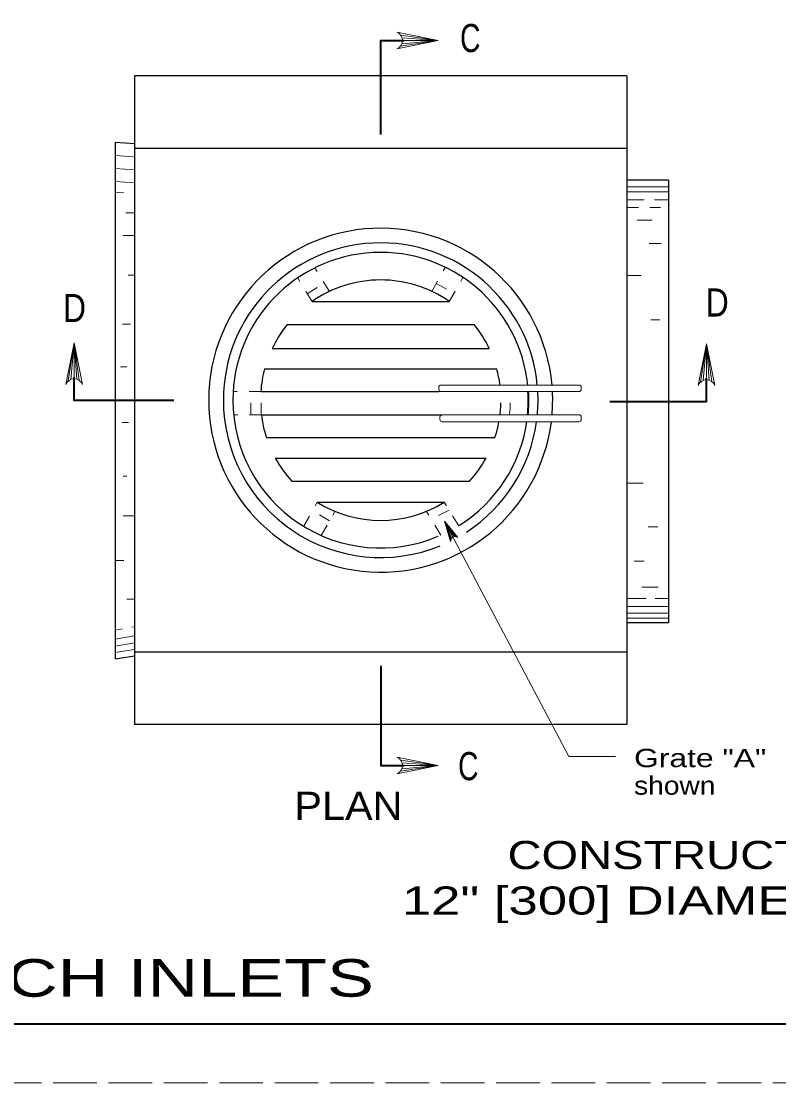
# Model space of a CAD drawing. Extents: x 1036.7 to 1070.7, y 883.9 to 905.9.
# Drawn here: x 1051.03 to 1057.49, y 883.91 to 892.96 of the extents above; entities that cross this region are included whole.
import ezdxf
from ezdxf.enums import TextEntityAlignment as Align

# ---------------------------------------------------------------- set-up
doc = ezdxf.new("R2010")
doc.units = 0
doc.header["$LTSCALE"] = 0.062
doc.linetypes.add('LONG_DASHED', pattern=[7.5, 6, -1.5])
doc.linetypes.add('SHORT_DASHED', pattern=[2.7, 1.5, -1.2])
doc.layers.add('1', color=7, linetype='Continuous', lineweight=13)

msp = doc.modelspace()

# ---------------------------------------------------------------- linework, layer by layer
at = {"layer": '1'}
for p, q in [((1054.26425, 892.74675), (1054.5885, 892.79633)), ((1054.268, 892.84117), (1054.5885, 892.79633)), ((1054.2765, 892.7675), (1054.5885, 892.79633)), ((1054.27892, 892.81892), (1054.5885, 892.79633)), ((1054.28217, 892.79633), (1054.5885, 892.79633)), ((1051.83217, 891.81367), (1051.99033, 891.80275)), ((1051.83217, 891.70508), (1051.99825, 891.69367)), ((1051.83217, 891.59333), (1051.99825, 891.58183)), ((1051.83217, 891.502), (1051.90658, 891.49683)), ((1056.19583, 891.54758), (1056.55183, 891.54758)), ((1056.19583, 891.50567), (1056.55183, 891.50567)), ((1056.19583, 891.4365), (1056.34217, 891.4365)), ((1056.43225, 891.4365), (1056.55183, 891.4365)), ((1051.92533, 891.32533), (1051.99825, 891.32533)), ((1056.19583, 891.3725), (1056.29525, 891.3725)), ((1056.39158, 891.3725), (1056.48383, 891.3725)), ((1056.2835, 891.26333), (1056.41108, 891.26333)), ((1051.90225, 891.13333), (1051.99825, 891.13333)), ((1056.38533, 891.06517), (1056.48858, 891.06517)), ((1051.9445, 890.7955), (1051.99825, 890.7955)), ((1056.19583, 890.791), (1056.31667, 890.791)), ((1056.40142, 890.41283), (1056.4775, 890.41283)), ((1051.89458, 890.37692), (1051.96367, 890.37692)), ((1051.433, 889.89275), (1051.48258, 890.217)), ((1051.45375, 889.905), (1051.48258, 890.217)), ((1051.48258, 889.91067), (1051.48258, 890.217)), ((1051.50525, 889.90733), (1051.48258, 890.217)), ((1051.52742, 889.8965), (1051.48258, 890.217)), ((1056.82508, 889.88358), (1056.87458, 890.20783)), ((1056.84583, 889.89583), (1056.87458, 890.20783)), ((1056.87458, 889.9015), (1056.87458, 890.20783)), ((1056.89725, 889.89817), (1056.87458, 890.20783)), ((1056.91942, 889.88733), (1056.87458, 890.20783)), ((1051.87933, 890.01208), (1051.933, 890.01208)), ((1054.59267, 889.83683), (1054.59267, 889.82117)), ((1054.59267, 889.80125), (1055.78667, 889.80125)), ((1054.61267, 889.85683), (1055.78667, 889.85683)), ((1055.80667, 889.83683), (1055.80667, 889.82117)), ((1054.6225, 889.60492), (1055.78667, 889.60492)), ((1051.89358, 889.53692), (1051.94733, 889.53692)), ((1054.6025, 889.58492), (1054.6025, 889.56492)), ((1054.6225, 889.54492), (1055.78667, 889.54492)), ((1055.80667, 889.58492), (1055.80667, 889.56492)), ((1051.90183, 889.08083), (1051.93117, 889.08083)), ((1056.19583, 889.0215), (1056.33592, 889.0215)), ((1051.90167, 888.74167), (1051.99825, 888.74167)), ((1054.71342, 888.56108), (1054.64175, 888.69642)), ((1054.70208, 888.55183), (1054.64175, 888.69642)), ((1054.69575, 888.54158), (1054.64175, 888.69642)), ((1054.72425, 888.56492), (1054.64175, 888.69642)), ((1054.73658, 888.56533), (1054.64175, 888.69642)), ((1056.37817, 888.6475), (1056.4605, 888.6475)), ((1051.83217, 888.36217), (1051.907, 888.36217)), ((1056.25892, 888.35708), (1056.34233, 888.35708)), ((1056.32342, 888.13442), (1056.46342, 888.13442)), ((1051.9315, 888.03108), (1051.99825, 888.03108)), ((1056.19583, 888.03842), (1056.36167, 888.03842)), ((1056.19583, 887.96958), (1056.55183, 887.96958)), ((1056.4365, 888.03842), (1056.55183, 888.03842)), ((1056.19583, 887.91333), (1056.55183, 887.91333)), ((1056.19583, 887.87025), (1056.55183, 887.87025)), ((1051.97592, 887.792), (1051.99825, 887.79558)), ((1051.83217, 887.76875), (1051.89608, 887.77908)), ((1051.83217, 887.69183), (1051.99825, 887.71875)), ((1051.83217, 887.63133), (1051.99825, 887.65817)), ((1051.83217, 887.57642), (1051.99825, 887.60333)), ((1054.26425, 886.564), (1054.5885, 886.61358)), ((1054.268, 886.65842), (1054.5885, 886.61358)), ((1054.2765, 886.58475), (1054.5885, 886.61358)), ((1054.27892, 886.63625), (1054.5885, 886.61358)), ((1054.28217, 886.61358), (1054.5885, 886.61358))]:
    msp.add_line(p, q, dxfattribs=at)
at = {"layer": '1', "lineweight": 25}
for p, q in [((1056.19583, 892.494), (1051.99825, 892.494)), ((1051.99825, 892.494), (1051.99825, 886.96275)), ((1056.19583, 892.494), (1056.19583, 886.96275)), ((1051.83217, 891.92808), (1051.83217, 887.52317)), ((1051.83217, 891.92808), (1051.99825, 891.91658)), ((1056.19583, 891.87417), (1051.99825, 891.87417)), ((1056.55183, 891.60392), (1056.19583, 891.60392)), ((1056.55183, 891.60392), (1056.55183, 887.829)), ((1053.51208, 890.57025), (1054.68208, 890.57025)), ((1053.30092, 890.37425), (1054.89333, 890.37425)), ((1053.17125, 890.16875), (1055.02292, 890.16875)), ((1053.10758, 889.99633), (1055.08658, 889.99633)), ((1053.0745, 889.80125), (1054.59267, 889.80125)), ((1053.07933, 889.60492), (1054.6225, 889.60492)), ((1053.12283, 889.40933), (1055.07142, 889.40933)), ((1053.1985, 889.23492), (1054.99567, 889.23492)), ((1053.33858, 889.03875), (1054.85558, 889.03875)), ((1053.55533, 888.85808), (1054.63875, 888.85808)), ((1056.55183, 887.829), (1056.19583, 887.829)), ((1051.83217, 887.52317), (1051.99825, 887.55008)), ((1056.19583, 887.57975), (1051.99825, 887.57975)), ((1056.19583, 886.96275), (1051.99825, 886.96275))]:
    msp.add_line(p, q, dxfattribs=at)
at = {"layer": '1', "linetype": 'SHORT_DASHED'}
for p, q in [((1054.53292, 890.65633), (1054.64858, 890.86175)), ((1053.51208, 890.57025), (1053.38917, 890.77125)), ((1053.65925, 890.65533), (1053.53583, 890.857)), ((1054.68208, 890.57025), (1054.79792, 890.77608)), ((1053.4715, 890.63658), (1053.61642, 890.72525)), ((1054.57108, 890.72417), (1054.72233, 890.64192)), ((1053.0745, 889.80125), (1052.83867, 889.80125)), ((1052.99092, 889.60492), (1052.99092, 889.80125)), ((1053.07933, 889.60492), (1053.0745, 889.80125)), ((1053.07933, 889.60492), (1052.84258, 889.60492)), ((1053.43967, 888.65267), (1053.55533, 888.85808)), ((1053.66175, 888.70092), (1053.51375, 888.78442)), ((1053.5905, 888.57433), (1053.70667, 888.78058)), ((1054.611, 888.57758), (1054.487, 888.78042)), ((1054.67958, 888.79142), (1054.52717, 888.71483)), ((1054.76208, 888.65642), (1054.63875, 888.85808))]:
    msp.add_line(p, q, dxfattribs=at)
at = {"layer": '1', "linetype": 'LONG_DASHED'}
msp.add_lwpolyline([(1036.67333, 883.90825), (1070.67333, 883.90825), (1070.67333, 905.90825), (1036.67333, 905.90825)], close=True, dxfattribs=at)
at = {"layer": '1', "lineweight": 25}
msp.add_lwpolyline([(1070.17333, 884.40825), (1038.67333, 884.40825), (1038.67333, 905.40825)], dxfattribs=at)
at = {"layer": '1', "lineweight": 40}
msp.add_lwpolyline([(1038.67333, 905.40825), (1070.17333, 905.40825), (1070.17333, 884.40825), (1038.67333, 884.40825)], close=True, dxfattribs=at)
msp.add_lwpolyline([(1038.67333, 905.40825), (1070.17333, 905.40825), (1070.17333, 884.40825), (1038.67333, 884.40825)], close=True, dxfattribs=at)
at = {"layer": '1'}
for points in [[(1054.2345, 892.7255), (1054.5885, 892.79633), (1054.2345, 892.86708)], [(1051.41175, 889.863), (1051.48258, 890.217), (1051.55333, 889.863)], [(1056.80383, 889.85383), (1056.87458, 890.20783), (1056.94542, 889.85383)], [(1054.64175, 888.69642), (1055.70075, 886.68992), (1056.1, 886.68992)], [(1054.69333, 888.5235), (1054.64175, 888.69642), (1054.75592, 888.55658)], [(1054.2345, 886.54275), (1054.5885, 886.61358), (1054.2345, 886.68433)]]:
    msp.add_lwpolyline(points, dxfattribs=at)
at = {"layer": '1', "lineweight": 35}
for points in [[(1054.09708, 891.99425), (1054.09708, 892.79633), (1054.297, 892.79633)], [(1052.33192, 889.72558), (1051.48258, 889.72558), (1051.48258, 889.9255)], [(1056.05208, 889.71642), (1056.87458, 889.71642), (1056.87458, 889.91633)], [(1054.09708, 887.4625), (1054.09708, 886.61358), (1054.297, 886.61358)]]:
    msp.add_lwpolyline(points, dxfattribs=at)
at = {"layer": '1'}
for centre, radius, start, end in [((1054.20593, 892.79633), 0.0764, 292.08605, 67.91218), ((1051.48264, 889.83439), 0.0764, 22.08782, 157.91395), ((1056.87469, 889.82522), 0.0764, 22.08782, 157.91395), ((1054.73132, 888.52744), 0.0382, 50.00073, 185.82686), ((1054.20593, 886.61363), 0.0764, 292.08605, 67.91218)]:
    msp.add_arc(centre, radius, start, end, dxfattribs=at)
at = {"layer": '1', "lineweight": 25}
for major_axis, start_param, end_param in [((1.4665, 0), 0.0876948, 3.1415927), ((1.34162, 0), 0.0958816, 3.1415927), ((1.26052, 0), 0.102071, 3.1415927), ((1.0252, 0), 1.5707963, 2.1779972), ((1.0252, 0), 0.9635714, 1.5707963), ((1.0252, 0), 2.4600993, 2.6976059), ((1.0252, 0), 0.4439896, 0.6815166), ((1.0252, 0), 2.8771221, 3.0705493), ((1.0252, 0), 0.1256121, 0.2644492), ((1.34162, 0), 6.190983, 6.3374741), ((1.4665, 0), 6.198854, 6.3328471), ((1.4665, 0), 3.1415927, 6.1577306), ((1.34162, 0), 3.1415927, 5.1008617), ((1.26052, 0), 3.1415927, 5.1128519), ((1.0252, 0), 3.2624097, 3.4580877), ((1.26052, 0), 5.2750037, 6.1370942), ((1.34162, 0), 5.288253, 6.1459824), ((1.0252, 0), 5.966676, 6.1032296), ((1.0252, 0), 3.6437937, 3.8796018), ((1.0252, 0), 5.5452008, 5.7809401), ((1.0252, 0), 4.1556647, 5.269042)]:
    msp.add_ellipse((1054.09709, 889.72842), major_axis=major_axis, ratio=0.999895, start_param=start_param, end_param=end_param, dxfattribs=at)
at = {"layer": '1'}
for centre, major_axis, start_param, end_param in [((1054.61268, 889.83686), (0.01999, 0), 1.5707963, 3.1415927), ((1054.61268, 889.8212), (-0.01999, 0), 6.2831853, 7.8539816), ((1055.78671, 889.83686), (0.01999, 0), 6.2831853, 7.8539816), ((1055.78671, 889.8212), (0.01999, 0), 4.712389, 6.2831853), ((1054.62251, 889.58492), (0.01999, 0), 1.5707963, 3.1415927), ((1055.78671, 889.58492), (0.01999, 0), 6.2831853, 7.8539816), ((1054.62251, 889.56493), (-0.01999, 0), 6.2831853, 7.8539816), ((1055.78671, 889.56493), (0.01999, 0), 4.712389, 6.2831853)]:
    msp.add_ellipse(centre, major_axis=major_axis, ratio=0.999895, start_param=start_param, end_param=end_param, dxfattribs=at)
at = {"layer": '1', "linetype": 'SHORT_DASHED', "lineweight": 25}
msp.add_ellipse((1054.05436, 889.72922), major_axis=(1.06776, 0), ratio=0.999895, start_param=6.1664924, end_param=6.3506731, dxfattribs=at)
at = {"layer": '1', "linetype": 'SHORT_DASHED'}
msp.add_ellipse((1054.05436, 889.72922), major_axis=(1.14773, 0), ratio=0.999895, start_param=6.1746556, end_param=6.3459648, dxfattribs=at)
at = {"layer": '1', "lineweight": 35}
msp.add_ellipse((1054.09709, 889.72842), major_axis=(1.26052, 0), ratio=0.999895, start_param=6.1850326, end_param=6.3409705, dxfattribs=at)

# ---------------------------------------------------------------- texts
at = {"layer": '1'}
for s, height, width, p in [('C', 0.24, 0.75, (1054.774, 892.69667)), ('D', 0.24, 0.85, (1056.86775, 890.44183)), ('D', 0.24, 0.85, (1051.38742, 890.3945)), ('C', 0.24, 0.75, (1054.757, 886.48825)), ('Grate "A"', 0.156, 1.3, (1056.25758, 886.59933)), ('shown', 0.156, 1.15, (1056.25758, 886.36467)), ('PLAN', 0.24, 1.1, (1053.361, 886.14983)), ('SIDE DITCH INLETS', 0.32, 1.4, (1048.38025, 884.64225))]:
    msp.add_text(s, height=height, dxfattribs=dict(at, width=width)).set_placement(p)
for s, width, p in [('CONSTRUCTED ON PIPE', 1.25, (1057.58579, 885.73042)), ('12" [300] DIAMETER OR OVER', 1.4, (1057.49079, 885.34208))]:
    msp.add_text(s, height=0.24, dxfattribs=dict(at, width=width)).set_placement(p, align=Align.CENTER)

doc.saveas('drawing.dxf')
